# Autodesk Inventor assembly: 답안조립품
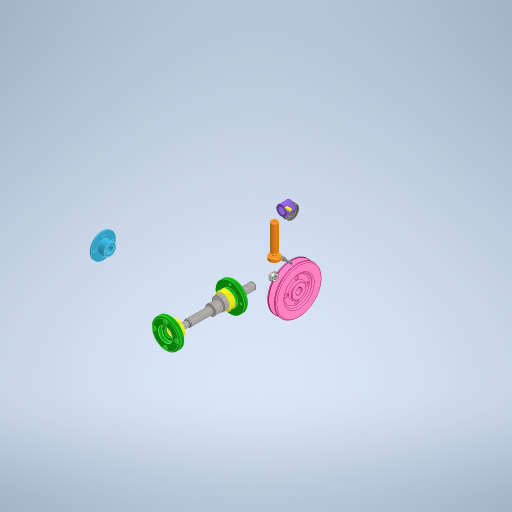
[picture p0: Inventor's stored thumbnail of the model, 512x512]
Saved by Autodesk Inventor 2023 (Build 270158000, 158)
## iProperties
Created: 2023-07
Part Number: 답안조립품
Document SubType Name: Assembly
Designer: Owner
Author: Owner
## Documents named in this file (16)
- C:\Users\Owner\Desktop\730711V1001\답안조립품.iam
- C:\Users\Owner\Desktop\730711V1001\본체.ipt
- C:\Users\Owner\Desktop\730711V1001\V-벨트풀리.ipt
- C:\Users\Owner\Desktop\730711V1001\너트 M8.ipt
- C:\Users\Owner\Desktop\730711V1001\뒤커버.ipt
- C:\Users\Owner\Desktop\730711V1001\베어링- 6202.ipt
- KS B 2023 - 6202 - 15 x 35 x 11 - 7.8.ipt
- C:\Users\Owner\Desktop\730711V1001\볼트 M4 x 12.ipt
- C:\Users\Owner\Desktop\730711V1001\볼트 M4 x 16.ipt
- C:\Users\Owner\Desktop\730711V1001\상부커버.ipt
- C:\Users\Owner\Desktop\730711V1001\슬라이드.ipt
- C:\Users\Owner\Desktop\730711V1001\앞커버.ipt
- C:\Users\Owner\Desktop\730711V1001\오일실 15 30 7.ipt
- C:\Users\Owner\Desktop\730711V1001\칼라.ipt
- C:\Users\Owner\Desktop\730711V1001\키 4 x 4 x 12.ipt
- C:\Users\Owner\Desktop\730711V1001\편심축.ipt
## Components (5 placed, 4 different names)
1. V-벨트풀리:1
2. KS B 2023 - 6202 - 15 x 35 x 11 - 7.8:1
3. KS B 1021 - 에 따름 ISO 1207 - 미터 A  M 4 x 12:1
4. ISO 4762 M4 x 16:1
5. KS B 2023 - 6202 - 15 x 35 x 11 - 7.8:2
